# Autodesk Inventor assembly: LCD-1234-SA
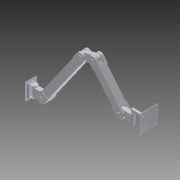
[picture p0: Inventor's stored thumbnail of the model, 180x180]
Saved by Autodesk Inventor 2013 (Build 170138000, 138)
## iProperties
Created: 2004-11
Part Number: LCD-1234-SA
Document SubType Name: Assembly
Designer: Autodesk, Inc.
Manufacturer: Standard
Standards Organization: Custom
Description: SWING ARM, LCD FLAT PANEL
Mass: 1844.57 g
Surface Area: 2731.03 cm^2
Volume: 1844.57 cm^3
Density: 1 g/cm^3
CAGE: 1LJX3
Dept. ID: Product Design
Description #2: ---
Finish #1: ---
Finish #2: ---
Material ID: ---
Project Number: ---
Author: Autodesk, Inc.
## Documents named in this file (7)
- Z:\_DATEN\Test Station\Components\SwingArm.iam
- Z:\_DATEN\Test Station\Components\BasePivot.ipt
- Z:\_DATEN\Test Station\Components\LongArm.ipt
- Z:\_DATEN\Test Station\Components\Joint.ipt
- Z:\_DATEN\Test Station\Components\ShortArm.ipt
- Z:\_DATEN\Test Station\Components\MonitorMount.ipt
- Z:\_DATEN\Test Station\Components\WallMount.ipt
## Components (7 placed, 6 different names)
1. WallMount:1 — Insert:6, Angle:1
2. BasePivot:1 — Insert:1, Insert:6, Angle:1
3. LongArm:1 — Insert:1, Insert:2
4. Joint:1 — Insert:2, Insert:3
5. ShortArm:1 — Insert:3, Insert:4
6. BasePivot:2 — Insert:4, Insert:5
7. MonitorMount:1 — Insert:5
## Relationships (7: Insert 6, Angle 1)
- Insert:1: BasePivot:1 ↔ LongArm:1
- Insert:2: LongArm:1 ↔ Joint:1
- Insert:3: Joint:1 ↔ ShortArm:1
- Insert:4: ShortArm:1 ↔ BasePivot:2
- Insert:5: BasePivot:2 ↔ MonitorMount:1
- Insert:6: WallMount:1 ↔ BasePivot:1
- Angle:1: WallMount:1 ↔ BasePivot:1
